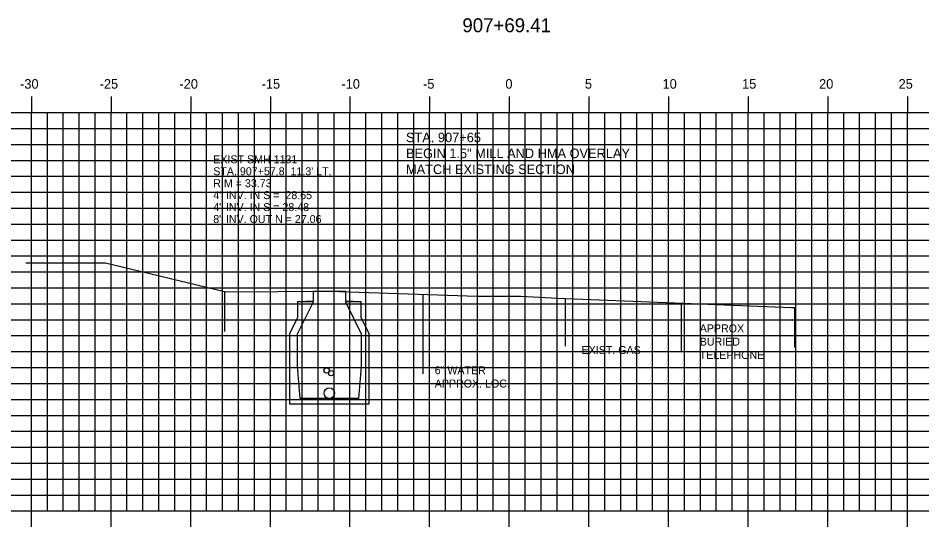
# Model space of a CAD drawing. Extents: x 1025909 to 1026079, y 394697 to 394807.
# Drawn here: x 1025960.8 to 1026017.6, y 394739.6 to 394771.5 of the extents above; entities that cross this region are included whole.
import ezdxf

# ---------------------------------------------------------------- set-up
doc = ezdxf.new("R2010")
doc.units = 0
for name, color, linetype in [('ANNOTATION', 7, 'Continuous'), ('D_Text_Monospaced', 7, 'Continuous'), ('H_V ANNOTATION', 7, 'Continuous'), ('MAJOR', 7, 'Continuous'), ('MINOR', 7, 'Continuous'), ('S_Roadway_Centerline', 7, 'Continuous'), ('S_Roadway_Edge_Pavement', 7, 'Continuous'), ('S_Utilities_UG_Gas_Line', 7, 'Continuous'), ('S_Utilities_UG_Sanitary_MH', 7, 'Continuous'), ('S_Utilities_UG_Sanitary_Sewer', 7, 'Continuous'), ('S_Utilities_UG_Water_Line', 7, 'Continuous')]:
    doc.layers.add(name, color=color, linetype=linetype)

msp = doc.modelspace()

# ---------------------------------------------------------------- linework, layer by layer
at = {"layer": 'MAJOR'}
for p, q in [((1025961.677, 394766.609), (1025961.677, 394765.607)), ((1025966.677, 394766.609), (1025966.677, 394765.607)), ((1025971.677, 394766.609), (1025971.677, 394765.607)), ((1025976.677, 394766.609), (1025976.677, 394765.607)), ((1025981.677, 394766.609), (1025981.677, 394765.607)), ((1025986.677, 394766.609), (1025986.677, 394765.607)), ((1025991.677, 394766.609), (1025991.677, 394765.607)), ((1025996.677, 394766.609), (1025996.677, 394765.607)), ((1026001.677, 394766.609), (1026001.677, 394765.607)), ((1026006.677, 394766.609), (1026006.677, 394765.607)), ((1026011.677, 394766.609), (1026011.677, 394765.607)), ((1026016.677, 394766.609), (1026016.677, 394765.607)), ((1025921.677, 394765.607), (1026061.677, 394765.607)), ((1025961.677, 394740.607), (1025961.677, 394765.607)), ((1025966.677, 394740.607), (1025966.677, 394765.607)), ((1025971.677, 394740.607), (1025971.677, 394765.607)), ((1025976.677, 394740.607), (1025976.677, 394765.607)), ((1025981.677, 394740.607), (1025981.677, 394765.607)), ((1025986.677, 394740.607), (1025986.677, 394765.607)), ((1025991.677, 394740.607), (1025991.677, 394765.607)), ((1025996.677, 394740.607), (1025996.677, 394765.607)), ((1026001.677, 394740.607), (1026001.677, 394765.607)), ((1026006.677, 394740.607), (1026006.677, 394765.607)), ((1026011.677, 394740.607), (1026011.677, 394765.607)), ((1025921.677, 394760.607), (1026061.677, 394760.607)), ((1025921.677, 394755.607), (1026061.677, 394755.607)), ((1025921.677, 394750.607), (1026061.677, 394750.607)), ((1025921.677, 394745.607), (1026061.677, 394745.607)), ((1025921.677, 394740.607), (1026061.677, 394740.607)), ((1025961.677, 394739.605), (1025961.677, 394740.607)), ((1025966.677, 394739.605), (1025966.677, 394740.607)), ((1025971.677, 394739.605), (1025971.677, 394740.607)), ((1025976.677, 394739.605), (1025976.677, 394740.607)), ((1025981.677, 394739.605), (1025981.677, 394740.607)), ((1025986.677, 394739.605), (1025986.677, 394740.607)), ((1025991.677, 394739.605), (1025991.677, 394740.607)), ((1025996.677, 394739.605), (1025996.677, 394740.607)), ((1026001.677, 394739.605), (1026001.677, 394740.607)), ((1026006.677, 394739.605), (1026006.677, 394740.607)), ((1026011.677, 394739.605), (1026011.677, 394740.607)), ((1026016.677, 394739.605), (1026016.677, 394740.607))]:
    msp.add_line(p, q, dxfattribs=at)
at = {"layer": 'MINOR'}
for p, q in [((1025962.677, 394740.607), (1025962.677, 394765.607)), ((1025963.677, 394740.607), (1025963.677, 394765.607)), ((1025964.677, 394740.607), (1025964.677, 394765.607)), ((1025965.677, 394740.607), (1025965.677, 394765.607)), ((1025967.677, 394740.607), (1025967.677, 394765.607)), ((1025968.677, 394740.607), (1025968.677, 394765.607)), ((1025969.677, 394740.607), (1025969.677, 394765.607)), ((1025970.677, 394740.607), (1025970.677, 394765.607)), ((1025972.677, 394740.607), (1025972.677, 394765.607)), ((1025973.677, 394740.607), (1025973.677, 394765.607)), ((1025974.677, 394740.607), (1025974.677, 394765.607)), ((1025975.677, 394740.607), (1025975.677, 394765.607)), ((1025977.677, 394740.607), (1025977.677, 394765.607)), ((1025978.677, 394740.607), (1025978.677, 394765.607)), ((1025979.677, 394740.607), (1025979.677, 394765.607)), ((1025980.677, 394740.607), (1025980.677, 394765.607)), ((1025982.677, 394740.607), (1025982.677, 394765.607)), ((1025983.677, 394740.607), (1025983.677, 394765.607)), ((1025984.677, 394740.607), (1025984.677, 394765.607)), ((1025985.677, 394740.607), (1025985.677, 394765.607)), ((1025987.677, 394740.607), (1025987.677, 394765.607)), ((1025988.677, 394740.607), (1025988.677, 394765.607)), ((1025989.677, 394740.607), (1025989.677, 394765.607)), ((1025990.677, 394740.607), (1025990.677, 394765.607)), ((1025992.677, 394740.607), (1025992.677, 394765.607)), ((1025993.677, 394740.607), (1025993.677, 394765.607)), ((1025994.677, 394740.607), (1025994.677, 394765.607)), ((1025995.677, 394740.607), (1025995.677, 394765.607)), ((1025997.677, 394740.607), (1025997.677, 394765.607)), ((1025998.677, 394740.607), (1025998.677, 394765.607)), ((1025999.677, 394740.607), (1025999.677, 394765.607)), ((1026000.677, 394740.607), (1026000.677, 394765.607)), ((1026002.677, 394740.607), (1026002.677, 394765.607)), ((1026003.677, 394740.607), (1026003.677, 394765.607)), ((1026004.677, 394740.607), (1026004.677, 394765.607)), ((1026005.677, 394740.607), (1026005.677, 394765.607)), ((1026007.677, 394740.607), (1026007.677, 394765.607)), ((1026008.677, 394740.607), (1026008.677, 394765.607)), ((1026009.677, 394740.607), (1026009.677, 394765.607)), ((1026010.677, 394740.607), (1026010.677, 394765.607)), ((1026012.677, 394740.607), (1026012.677, 394765.607)), ((1026013.677, 394740.607), (1026013.677, 394765.607)), ((1026014.677, 394740.607), (1026014.677, 394765.607)), ((1026015.677, 394740.607), (1026015.677, 394765.607)), ((1026016.677, 394740.607), (1026016.677, 394765.607)), ((1025921.677, 394764.607), (1026061.677, 394764.607)), ((1025921.677, 394763.607), (1026061.677, 394763.607)), ((1025921.677, 394762.607), (1026061.677, 394762.607)), ((1025921.677, 394761.607), (1026061.677, 394761.607)), ((1025921.677, 394759.607), (1026061.677, 394759.607)), ((1025921.677, 394758.607), (1026061.677, 394758.607)), ((1025921.677, 394757.607), (1026061.677, 394757.607)), ((1025921.677, 394756.607), (1026061.677, 394756.607)), ((1025921.677, 394754.607), (1026061.677, 394754.607)), ((1025921.677, 394753.607), (1026061.677, 394753.607)), ((1025921.677, 394752.607), (1026061.677, 394752.607)), ((1025921.677, 394751.607), (1026061.677, 394751.607)), ((1025921.677, 394749.607), (1026061.677, 394749.607)), ((1025921.677, 394748.607), (1026061.677, 394748.607)), ((1025921.677, 394747.607), (1026061.677, 394747.607)), ((1025921.677, 394746.607), (1026061.677, 394746.607)), ((1025921.677, 394744.607), (1026061.677, 394744.607)), ((1025921.677, 394743.607), (1026061.677, 394743.607)), ((1025921.677, 394742.607), (1026061.677, 394742.607)), ((1025921.677, 394741.607), (1026061.677, 394741.607))]:
    msp.add_line(p, q, dxfattribs=at)
at = {"layer": 'S_Roadway_Centerline'}
msp.add_lwpolyline([(1025961.317, 394756.184), (1025961.344, 394756.181), (1025961.381, 394756.176), (1025966.333, 394756.183), (1025973.795, 394754.374), (1025973.922, 394754.362), (1025980.395, 394754.395), (1025989.673, 394754.095), (1025992.394, 394754.087), (1025994.705, 394753.969), (1026009.407, 394753.366), (1026009.592, 394753.369)], dxfattribs=at)
at = {"layer": 'S_Roadway_Edge_Pavement'}
for p, q in [((1025973.795, 394754.374), (1025973.795, 394751.874)), ((1026009.592, 394753.369), (1026009.592, 394750.869))]:
    msp.add_line(p, q, dxfattribs=at)
at = {"layer": 'S_Utilities_UG_Gas_Line'}
msp.add_line((1025995.179, 394753.95), (1025995.179, 394750.95), dxfattribs=at)
at = {"layer": 'S_Utilities_UG_Sanitary_MH'}
for p, q in [((1025978.377, 394751.728), (1025979.395, 394753.73)), ((1025979.395, 394753.73), (1025978.377, 394753.73)), ((1025978.377, 394753.73), (1025978.377, 394752.745)), ((1025982.38, 394753.73), (1025981.396, 394753.73)), ((1025981.396, 394753.73), (1025982.38, 394751.728)), ((1025982.38, 394752.745), (1025982.38, 394753.73)), ((1025978.377, 394752.745), (1025977.885, 394751.728)), ((1025982.872, 394751.728), (1025982.38, 394752.745)), ((1025977.885, 394751.728), (1025977.885, 394747.339)), ((1025978.377, 394749.668), (1025978.377, 394751.728)), ((1025982.38, 394751.728), (1025982.38, 394749.668)), ((1025982.872, 394747.339), (1025982.872, 394751.728)), ((1025978.542, 394747.667), (1025978.377, 394749.668)), ((1025982.38, 394749.668), (1025982.216, 394747.667)), ((1025982.216, 394747.667), (1025978.542, 394747.667)), ((1025977.885, 394747.339), (1025982.872, 394747.339))]:
    msp.add_line(p, q, dxfattribs=at)
msp.add_lwpolyline([(1025978.902, 394753.771), (1025979.395, 394753.771), (1025979.395, 394754.395), (1025981.396, 394754.395), (1025981.396, 394753.771), (1025981.888, 394753.771)], dxfattribs=at)
at = {"layer": 'S_Utilities_UG_Sanitary_Sewer'}
for centre, radius in [((1025980.212, 394749.423), 0.167), ((1025980.497, 394749.253), 0.167), ((1025980.379, 394748), 0.333)]:
    msp.add_circle(centre, radius, dxfattribs=at)
at = {"layer": 'S_Utilities_UG_Water_Line'}
for p, q in [((1025986.25, 394754.206), (1025986.25, 394749.206)), ((1026002.477, 394753.65), (1026002.477, 394750.597))]:
    msp.add_line(p, q, dxfattribs=at)

# ---------------------------------------------------------------- texts
at = {"layer": 'ANNOTATION'}
for s, p in [('STA. 907+65', (1025985.194, 394763.748)), ('BEGIN 1.5" MILL AND HMA OVERLAY', (1025985.194, 394762.748)), ('MATCH EXISTING SECTION', (1025985.194, 394761.748))]:
    msp.add_text(s, height=0.6, dxfattribs=at).set_placement(p)
at = {"layer": 'D_Text_Monospaced'}
for s, height, p in [('EXIST SMH 1131', 0.49998, (1025973.094, 394762.425)), ("STA. 907+57.8, 11.3' LT.", 0.49998, (1025973.094, 394761.675)), ('RIM = 33.73', 0.49998, (1025973.094, 394760.925)), ('4" INV. IN S =  28.65', 0.49998, (1025973.094, 394760.175)), ('4" INV. IN S = 28.48', 0.49998, (1025973.094, 394759.426)), ('8" INV. OUT N = 27.06', 0.49998, (1025973.094, 394758.676)), ('APPROX', 0.5, (1026003.637, 394751.815)), ('BURIED ', 0.5, (1026003.637, 394750.982)), ('EXIST. GAS', 0.5, (1025996.219, 394750.455)), ('TELEPHONE', 0.5, (1026003.637, 394750.148)), ('6" WATER', 0.5, (1025986.998, 394749.186)), ('APPROX. LOC.', 0.49998, (1025986.998, 394748.352))]:
    msp.add_text(s, height=height, dxfattribs=at).set_placement(p)
at = {"layer": 'H_V ANNOTATION'}
for s, height, p in [('907+69.41', 0.875, (1025988.735, 394770.65)), ('-30', 0.6, (1025960.965, 394767.107)), ('-25', 0.6, (1025965.962, 394767.107)), ('-20', 0.6, (1025970.97, 394767.107)), ('-15', 0.6, (1025976.133, 394767.107)), ('-10', 0.6, (1025981.141, 394767.107)), ('-5', 0.6, (1025986.267, 394767.107)), ('0', 0.6, (1025991.436, 394767.107)), ('5', 0.6, (1025996.428, 394767.107)), ('10', 0.6, (1026001.302, 394767.107)), ('15', 0.6, (1026006.294, 394767.107)), ('20', 0.6, (1026011.131, 394767.107)), ('25', 0.6, (1026016.123, 394767.107))]:
    msp.add_text(s, height=height, dxfattribs=at).set_placement(p)
at = {"layer": 'S_Roadway_Centerline'}
for s, p in [('C', (1025992.389, 394754.087)), ('L', (1025992.394, 394754.08))]:
    msp.add_text(s, height=0.0146, dxfattribs=at).set_placement(p)

doc.saveas('drawing.dxf')
